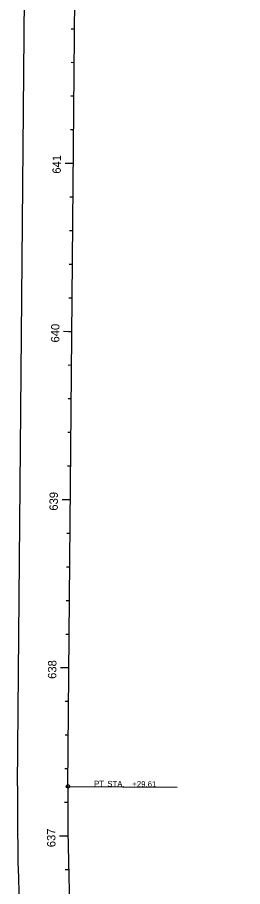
# Model space of a CAD drawing. Extents: x 2003883 to 2007688, y 399149 to 412300.
# Drawn here: x 2003910 to 2004044, y 410749 to 411266 of the extents above; entities that cross this region are included whole.
import ezdxf

# ---------------------------------------------------------------- set-up
doc = ezdxf.new("R2010")
doc.units = 0
for name, color, linetype in [('BaselineSurvey', 7, 'Continuous'), ('ConstLines', 7, 'Continuous'), ('Default', 7, 'Continuous'), ('TextAlgnCardinalPnt', 7, 'Continuous'), ('TextAlgnStation100', 7, 'Continuous'), ('TextAlgnStation1000', 7, 'Continuous'), ('TextAlgnStation500', 7, 'Continuous'), ('TextAlgnTicks100', 7, 'Continuous'), ('TextAlgnTicks1000', 7, 'Continuous'), ('TextAlgnTicks500', 7, 'Continuous'), ('TextAlgnTicks5000', 7, 'Continuous')]:
    doc.layers.add(name, color=color, linetype=linetype)

msp = doc.modelspace()

# ---------------------------------------------------------------- linework, layer by layer
at = {"layer": 'BaselineSurvey'}
msp.add_line((2003939.73, 410808.61), (2003953.03, 412299.6), dxfattribs=at)
msp.add_arc((2005402.52, 410795.56), 1462.84, 179.48905, 201.72713, dxfattribs=at)
at = {"layer": 'ConstLines'}
msp.add_line((2003909.74, 410808.88), (2003923.03, 412299.87), dxfattribs=at)
msp.add_arc((2005402.52, 410795.56), 1492.84, 179.48905, 201.72713, dxfattribs=at)
at = {"layer": 'Default'}
msp.add_line((2003939.73, 410808.61), (2003953.03, 412299.6), dxfattribs=at)
msp.add_arc((2005402.52, 410795.56), 1462.84, 179.48905, 201.72713, dxfattribs=at)
at = {"layer": 'TextAlgnCardinalPnt'}
msp.add_line((2003939.73, 410808.61), (2004004.73, 410808.03), dxfattribs=at)
msp.add_circle((2003939.73, 410808.61), 1, dxfattribs=at)
at = {"layer": 'TextAlgnTicks100'}
for p, q in [((2003943.75, 411258.98), (2003941.75, 411258.99)), ((2003943.57, 411238.98), (2003941.57, 411238.99)), ((2003943.39, 411218.98), (2003941.39, 411218.99)), ((2003943.22, 411198.98), (2003941.22, 411199)), ((2003943.04, 411178.98), (2003938.04, 411179.02)), ((2003942.86, 411158.98), (2003940.86, 411159)), ((2003942.68, 411138.98), (2003940.68, 411139)), ((2003942.5, 411118.98), (2003940.5, 411119)), ((2003942.32, 411098.98), (2003940.32, 411099)), ((2003942.15, 411078.98), (2003937.15, 411079.03)), ((2003941.97, 411058.98), (2003939.97, 411059)), ((2003941.79, 411038.98), (2003939.79, 411039)), ((2003941.61, 411018.98), (2003939.61, 411019)), ((2003941.43, 410998.99), (2003939.43, 410999)), ((2003941.25, 410978.99), (2003936.25, 410979.03)), ((2003941.08, 410958.99), (2003939.08, 410959)), ((2003940.9, 410938.99), (2003938.9, 410939.01)), ((2003940.72, 410918.99), (2003938.72, 410919.01)), ((2003940.54, 410898.99), (2003938.54, 410899.01)), ((2003940.36, 410878.99), (2003935.36, 410879.03)), ((2003940.18, 410858.99), (2003938.18, 410859.01)), ((2003940.01, 410838.99), (2003938.01, 410839.01)), ((2003939.83, 410818.99), (2003937.83, 410819.01)), ((2003939.68, 410798.99), (2003937.68, 410799)), ((2003939.77, 410778.99), (2003934.77, 410778.94)), ((2003940.13, 410759), (2003938.13, 410758.95))]:
    msp.add_line(p, q, dxfattribs=at)
at = {"layer": 'TextAlgnTicks1000'}
for p, q in [((2003942.15, 411078.98), (2003937.15, 411079.03)), ((2003940.36, 410878.99), (2003938.36, 410879.01))]:
    msp.add_line(p, q, dxfattribs=at)
at = {"layer": 'TextAlgnTicks500'}
for p, q in [((2003943.04, 411178.98), (2003941.04, 411179)), ((2003942.15, 411078.98), (2003937.15, 411079.03)), ((2003941.25, 410978.99), (2003939.25, 410979)), ((2003940.36, 410878.99), (2003938.36, 410879.01)), ((2003939.77, 410778.99), (2003937.77, 410778.97))]:
    msp.add_line(p, q, dxfattribs=at)
at = {"layer": 'TextAlgnTicks5000'}
msp.add_line((2003942.15, 411078.98), (2003940.15, 411079), dxfattribs=at)

# ---------------------------------------------------------------- texts
at = {"layer": 'TextAlgnCardinalPnt'}
for s, p in [('PT', (2003955.25, 410808.47)), (' STA. ', (2003961.83, 410808.41)), ('+29.61', (2003977.96, 410808.27))]:
    msp.add_text(s, height=3.48, rotation=359.489, dxfattribs=at).set_placement(p)
at = {"layer": 'TextAlgnStation100'}
for s, rotation, p in [('641', 89.489, (2003935.48, 411172.93)), ('640', 89.489, (2003934.59, 411072.55)), ('639', 89.489, (2003933.7, 410972.55)), ('638', 89.489, (2003932.8, 410872.51)), ('637', 90.649, (2003932.34, 410772.46))]:
    msp.add_text(s, height=4.98, rotation=rotation, dxfattribs=at).set_placement(p)
at = {"layer": 'TextAlgnStation1000'}
msp.add_text('640', height=4.98, rotation=89.489, dxfattribs=at).set_placement((2003934.59, 411072.55))
at = {"layer": 'TextAlgnStation500'}
msp.add_text('640', height=4.98, rotation=89.489, dxfattribs=at).set_placement((2003934.59, 411072.55))

doc.saveas('drawing.dxf')
